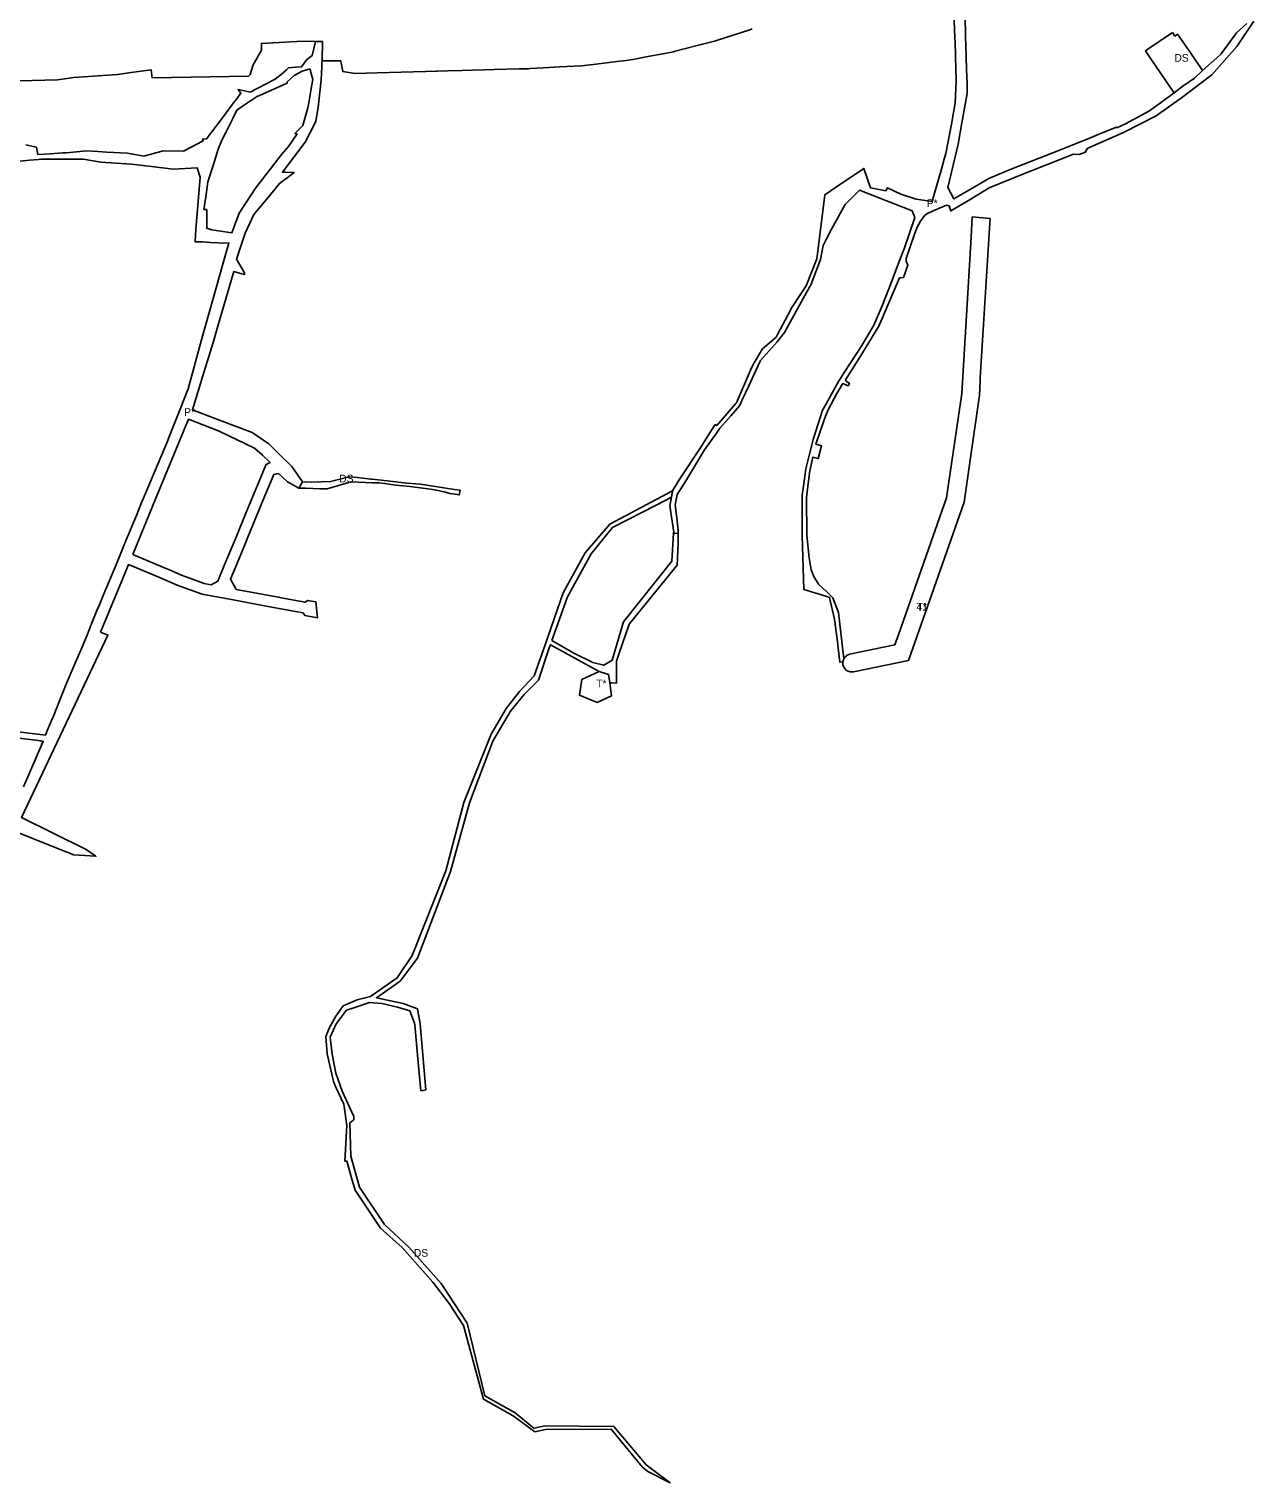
# Model space of a CAD drawing. Extents: x -501732 to -497665, y -1142022 to -1138283.
# Drawn here: x -498822 to -497699, y -1142022 to -1140690 of the extents above; entities that cross this region are included whole.
import ezdxf

# ---------------------------------------------------------------- set-up
doc = ezdxf.new("R2010")
doc.units = 0
for name, color, linetype in [('22', 7, 'Continuous'), ('23', 7, 'Continuous'), ('4', 7, 'Continuous'), ('43', 7, 'Continuous'), ('5', 7, 'Continuous'), ('61', 7, 'Continuous')]:
    doc.layers.add(name, color=color, linetype=linetype)

msp = doc.modelspace()

# ---------------------------------------------------------------- linework, layer by layer
at = {"layer": '22'}
msp.add_lwpolyline([(-498289.435, -1141289.365), (-498287.94, -1141301.37), (-498300.97, -1141307.29), (-498317.15, -1141300.48), (-498315.12, -1141286.35), (-498299.02, -1141279.08), (-498290.41, -1141281.54)], close=True, dxfattribs=at)
at = {"layer": '23'}
msp.add_lwpolyline([(-497940.79, -1140863.814), (-497941.059, -1140868.085), (-497950, -1141010), (-497950.085, -1141012.957), (-497950.453, -1141025.823), (-497959.442, -1141087.571), (-497964.714, -1141123.789), (-497965.056, -1141124.761), (-498015.675, -1141268.789), (-498064.477, -1141278.806), (-498066.144, -1141279.148), (-498069.236, -1141279.192), (-498070.925, -1141278.52), (-498072.345, -1141277.955), (-498074.707, -1141275.584), (-498075.885, -1141272.726), (-498075.895, -1141272.009), (-498075.921, -1141270.104), (-498075.928, -1141269.635), (-498074.954, -1141267.186), (-498074.691, -1141266.526), (-498072.598, -1141264.44), (-498072.32, -1141264.164), (-498069.462, -1141262.986), (-498068.179, -1141262.723), (-498028.144, -1141254.504), (-498024.601, -1141244.424), (-497980.812, -1141119.828), (-497966.901, -1141024.267), (-497958.345, -1140881.029), (-497957.238, -1140862.504), (-497954.3, -1140862.62)], close=True, dxfattribs=at)
at = {"layer": '4'}
for points in [[(-497773.83, -1140693.5), (-497771.55, -1140696.82), (-497769.08, -1140695.11), (-497756.35, -1140713.53), (-497746.3, -1140728.34), (-497753.47, -1140735.53), (-497759.27, -1140739.51), (-497765.07, -1140743.48), (-497772.17, -1140748.77), (-497775.117, -1140744.502), (-497794.317, -1140716.69), (-497798.59, -1140710.5), (-497796.43, -1140708.94)], [(-498574.31, -1141110.9), (-498570.89, -1141105.33), (-498562.596, -1141105.632), (-498545.15, -1141104.99), (-498536.71, -1141102.76), (-498528.28, -1141100.54), (-498520.46, -1141101.35), (-498508.39, -1141102.61), (-498507.39, -1141102.72), (-498498.55, -1141103.7), (-498475.36, -1141106.28), (-498462.89, -1141107.34), (-498431.68, -1141112.08), (-498426.531, -1141112.859), (-498427.26, -1141117.13), (-498433.33, -1141116.09), (-498435.81, -1141115.8), (-498441.2, -1141114.49), (-498449.94, -1141112.38), (-498453.72, -1141111.92), (-498472.53, -1141109.49), (-498478.88, -1141108.76), (-498485.35, -1141108.14), (-498489.86, -1141107.52), (-498495.46, -1141106.76), (-498500.85, -1141106.22), (-498507.19, -1141105.99), (-498513.1, -1141105.94), (-498526.27, -1141105.09), (-498535.71, -1141107.87), (-498548.32, -1141111.71), (-498554.617, -1141111.514), (-498567.931, -1141111.099)], [(-498342.431, -1141250.586), (-498322.306, -1141262), (-498305.064, -1141270.559), (-498294.892, -1141273.288), (-498287.22, -1141268.63), (-498276.94, -1141233.48), (-498232.47, -1141177.75), (-498230.861, -1141152.361), (-498226.765, -1141152.454), (-498226.85, -1141161.49), (-498227.64, -1141181.47), (-498271.5, -1141235.54), (-498275.18, -1141246.2), (-498277.34, -1141252.47), (-498280.96, -1141262.99), (-498283.2, -1141269.48), (-498283.26, -1141289.53), (-498287.32, -1141289.47), (-498289.435, -1141289.365), (-498290.41, -1141281.54), (-498299.02, -1141279.08), (-498343.818, -1141254.467), (-498344.82, -1141257.27), (-498354.69, -1141286.8), (-498367.96, -1141299.96), (-498380.22, -1141315.29), (-498396.49, -1141342.81), (-498418.05, -1141399.23), (-498435.49, -1141462.28), (-498465.58, -1141541.64), (-498481.37, -1141562.54), (-498503.245, -1141577.735), (-498478.577, -1141583.028), (-498465.718, -1141587.813), (-498463.01, -1141601.55), (-498458.03, -1141662.23), (-498460.46, -1141662.63), (-498462.48, -1141662.97), (-498464.9, -1141637.05), (-498468.16, -1141602.47), (-498468.3, -1141600.99), (-498472.52, -1141589.85), (-498483.89, -1141586.39), (-498498.32, -1141583.09), (-498509.53, -1141582.1), (-498523.91, -1141586.93), (-498530.63, -1141589.19), (-498540.19, -1141601.73), (-498545.55, -1141614.01), (-498543.68, -1141629.6), (-498540.35, -1141646.84), (-498534.51, -1141663.26), (-498524.04, -1141686.55), (-498524.02, -1141689.63), (-498527.53, -1141692.29), (-498526.77, -1141723.05), (-498518.8, -1141751.37), (-498495.69, -1141785.66), (-498473.4, -1141806.35), (-498444.04, -1141839.62), (-498420.03, -1141875.81), (-498403.77, -1141942.42), (-498375.96, -1141957.95), (-498358.83, -1141971.96), (-498348.77, -1141970.04), (-498285.68, -1141970.55), (-498256.16, -1142005.55), (-498234.08, -1142022.26), (-498254.59, -1142011.76), (-498259.65, -1142007.67), (-498288.05, -1141973.01), (-498348.22, -1141973.24), (-498358.19, -1141975.54), (-498377.9, -1141960.78), (-498405.21, -1141945.59), (-498423.37, -1141878.17), (-498436.54, -1141857.84), (-498451.59, -1141838.3), (-498479.77, -1141806.48), (-498499.6, -1141788.79), (-498522.72, -1141754.01), (-498525.92, -1141742.8), (-498530.29, -1141727.52), (-498532.03, -1141727.36), (-498530.34, -1141694.84), (-498533.18, -1141675.22), (-498540.46, -1141659.57), (-498542.66, -1141654.6), (-498548.259, -1141629.103), (-498549.654, -1141613.161), (-498546.605, -1141605.539), (-498540.508, -1141594.678), (-498533.648, -1141585.341), (-498520.882, -1141579.815), (-498508.726, -1141576.517), (-498484.13, -1141559.65), (-498470.47, -1141538.96), (-498439.71, -1141461.65), (-498423.24, -1141399.07), (-498398.03, -1141336.42), (-498384.43, -1141312.86), (-498372.17, -1141297.15), (-498358.52, -1141282.97), (-498348.596, -1141254.445), (-498332.09, -1141207), (-498311.8, -1141170.38), (-498289.43, -1141143.87), (-498231.89, -1141113.5), (-498232.81, -1141119.29), (-498246.24, -1141126.218), (-498286.74, -1141147.11), (-498306.4, -1141171.2), (-498328.13, -1141210.57)]]:
    msp.add_lwpolyline(points, close=True, dxfattribs=at)
at = {"layer": '43'}
for points in [[(-497964.62, -1140654.4), (-497963.48, -1140692.74), (-497963.31, -1140698.84), (-497963.1, -1140704.84), (-497962.425, -1140727.105), (-497962.01, -1140740.8), (-497961.95, -1140749.45), (-497966.8, -1140776.46), (-497970.28, -1140795.81), (-497979.66, -1140835.43), (-497974.23, -1140845.84), (-497956.22, -1140835.44), (-497942.02, -1140827.25), (-497922.43, -1140819.22), (-497902.98, -1140811.53), (-497883.42, -1140803.71), (-497862.51, -1140795.48), (-497848.25, -1140789.66), (-497844.06, -1140787.96), (-497838.09, -1140785.5), (-497825.15, -1140780.18), (-497824.82, -1140780.89), (-497816.79, -1140777.36), (-497794.67, -1140765.2), (-497772.17, -1140748.77), (-497765.07, -1140743.48), (-497759.27, -1140739.51), (-497753.47, -1140735.53), (-497746.3, -1140728.34), (-497730.5, -1140714.46), (-497729.76, -1140713.83), (-497729.17, -1140712.99), (-497715.23, -1140693.81), (-497705.51, -1140685.39)], [(-497699.12, -1140683.04), (-497714.85, -1140706.52), (-497737.64, -1140732.37), (-497765.45, -1140753.54), (-497788.84, -1140769.76), (-497818.59, -1140785.2), (-497851.87, -1140799.97), (-497853.39, -1140803.07), (-497859.19, -1140805.3), (-497864.48, -1140804.91), (-497913.92, -1140824.64), (-497920.78, -1140827.42), (-497941.6, -1140835.86), (-497960.66, -1140847.58), (-497977.01, -1140856.97), (-497978.25, -1140852.31), (-497980.78, -1140851.89), (-497993.14, -1140857.08), (-497998.1, -1140859.38), (-498000.68, -1140860.93), (-498004.77, -1140866.35), (-498007.61, -1140872.03), (-498010.54, -1140879.19), (-498017.69, -1140900.56), (-498017.81, -1140902.92), (-498016.39, -1140906.66), (-498020.37, -1140918.16), (-498023.87, -1140918.29), (-498038.33, -1140951.79), (-498042.95, -1140962.63), (-498061.04, -1140992.45), (-498073.33, -1141011.73), (-498072.82, -1141012.92), (-498069.8, -1141015.01), (-498070.83, -1141017.21), (-498075.72, -1141015.23), (-498081.28, -1141024.2), (-498088.95, -1141038.64), (-498091.8, -1141044.92), (-498096.11, -1141057.31), (-498100.54, -1141070.66), (-498095.36, -1141072.27), (-498098.52, -1141083.96), (-498103.39, -1141082.69), (-498106.07, -1141095.04), (-498108.095, -1141111.579), (-498109.11, -1141119.87), (-498108.84, -1141153.98), (-498106.55, -1141174.75), (-498104.84, -1141185.91), (-498102.41, -1141191.82), (-498098.14, -1141198.81), (-498090.9, -1141205.7), (-498084.99, -1141211.46), (-498079.95, -1141225), (-498074.954, -1141267.186), (-498075.928, -1141269.635), (-498075.921, -1141270.104), (-498078.55, -1141270.48), (-498081.13, -1141249.31), (-498083.09, -1141233.44), (-498083.44, -1141230.92), (-498087.32, -1141213.89), (-498087.97, -1141211.13), (-498091.49, -1141210.05), (-498111.43, -1141203.93), (-498113.1, -1141154.31), (-498113.11, -1141150.63), (-498113.18, -1141122.79), (-498113.13, -1141117.32), (-498111.999, -1141109.193), (-498109.78, -1141093.24), (-498102.94, -1141066.53), (-498094.35, -1141039.48), (-498091.41, -1141034.33), (-498079.45, -1141012.67), (-498079.21, -1141012.29), (-498074.51, -1141004.91), (-498058.47, -1140980.44), (-498047.36, -1140961.62), (-498039.9, -1140943.88), (-498031.5, -1140922.99), (-498026.57, -1140909.85), (-498020.61, -1140893.94), (-498020.06, -1140892.7), (-498009.83, -1140863.02), (-498012.27, -1140857), (-498060.53, -1140838.15), (-498073.71, -1140851.2), (-498086.17, -1140873.76), (-498090.72, -1140882.7), (-498093.71, -1140888.57), (-498096.28, -1140901.63), (-498104.91, -1140924.22), (-498112.09, -1140937.34), (-498127.53, -1140965.18), (-498129.24, -1140968.27), (-498135.88, -1140977.02), (-498151.12, -1140993.9), (-498155.49, -1141003.16), (-498162.09, -1141017.13), (-498168.13, -1141029.94), (-498170.6, -1141035.67), (-498178.36, -1141044.85), (-498188.4, -1141055.94), (-498191.645, -1141060.521), (-498202.54, -1141075.9), (-498218.99, -1141103.48), (-498224.74, -1141112.39), (-498227.71, -1141116.93), (-498229.52, -1141126.34), (-498227.94, -1141138.12), (-498226.74, -1141149.75), (-498226.765, -1141152.454), (-498230.861, -1141152.361), (-498230.8, -1141151.4), (-498234.36, -1141127.23), (-498232.81, -1141119.29), (-498231.89, -1141113.5), (-498225.81, -1141103.36), (-498206.05, -1141073.43), (-498196.069, -1141057.817), (-498192.81, -1141052.72), (-498191.37, -1141053.71), (-498174.09, -1141033.85), (-498173.23, -1141032.86), (-498159.51, -1141000.63), (-498157.02, -1140996.31), (-498149.59, -1140983.41), (-498137.06, -1140972.72), (-498135.73, -1140970.18), (-498126.2, -1140952.37), (-498122.42, -1140945.41), (-498114.24, -1140933.03), (-498109.42, -1140925.72), (-498099.64, -1140900.88), (-498098.06, -1140889.02), (-498092.19, -1140842.17), (-498082.41, -1140835.58), (-498056.55, -1140818.15), (-498050.47, -1140835.91), (-498036.37, -1140838.53), (-498035, -1140835.94), (-498022.72, -1140841.59), (-498008.56, -1140846.38), (-497994.03, -1140848.4), (-497992.47, -1140843.02), (-497985.454, -1140818.79), (-497982.83, -1140809.73), (-497981.55, -1140804.44), (-497976.28, -1140777.58), (-497973.02, -1140758.06), (-497972.55, -1140751.57), (-497971.9, -1140737.98), (-497972.51, -1140715.63), (-497972.65, -1140712.12), (-497973.3, -1140696.47), (-497973.452, -1140691.911), (-497973.8, -1140681.43)], [(-498824.4, -1140796.44), (-498814.65, -1140798.62), (-498813.42, -1140805.36), (-498802.05, -1140804.62), (-498790.422, -1140803.871), (-498787.31, -1140803.67), (-498768.83, -1140802.01), (-498758.28, -1140802.69), (-498750.12, -1140803.1), (-498731.35, -1140804.14), (-498716.27, -1140806.99), (-498698.54, -1140801.86), (-498680.14, -1140802.18), (-498662.02, -1140792.71), (-498662.47, -1140791.26), (-498658.87, -1140790.95), (-498644.35, -1140771.71), (-498634.95, -1140759.26), (-498631.56, -1140754.765), (-498627.43, -1140749.29), (-498630.06, -1140745.93), (-498624.23, -1140747.07), (-498618.83, -1140748.13), (-498612.57, -1140744.92), (-498595.88, -1140736.35), (-498594.44, -1140735.17), (-498590.47, -1140731.91), (-498585.66, -1140727.69), (-498583.65, -1140725.93), (-498577.09, -1140725.34), (-498571.85, -1140724.87), (-498567.11, -1140718.32), (-498562.15, -1140714.68), (-498559.063, -1140701.72), (-498552.643, -1140701.808), (-498553.06, -1140719.57), (-498553.11, -1140721.01), (-498553.249, -1140724.759), (-498553.7, -1140736.98), (-498556.49, -1140762.25), (-498558.75, -1140774.89), (-498559.97, -1140777.66), (-498568.52, -1140794.14), (-498589.38, -1140821.38), (-498586.65, -1140821.46), (-498578.61, -1140821.94), (-498584.95, -1140826.56), (-498590.754, -1140830.985), (-498591.98, -1140831.92), (-498602.77, -1140844.93), (-498615.59, -1140860.37), (-498623.59, -1140877.34), (-498630.29, -1140897.47), (-498631.5, -1140901.1), (-498624.03, -1140913.59), (-498624.01, -1140915.23), (-498626.53, -1140914.67), (-498633.99, -1140912.47), (-498647.79, -1140960.45), (-498650.35, -1140969.02), (-498652.268, -1140975.288), (-498655.37, -1140985.43), (-498661.35, -1141005.13), (-498671.72, -1141039.24), (-498649.34, -1141047.78), (-498617.19, -1141060.05), (-498601.76, -1141070.37), (-498596.36, -1141075.85), (-498592.62, -1141079.52), (-498580.66, -1141091.26), (-498570.89, -1141105.33), (-498574.31, -1141110.9), (-498584.82, -1141105.13), (-498592.82, -1141097.64), (-498597.27, -1141098.41), (-498606.94, -1141121.79), (-498616.69, -1141145.36), (-498617.65, -1141147.67), (-498627.58, -1141171.69), (-498636.97, -1141194.38), (-498631.63, -1141203.78), (-498593.1, -1141210.93), (-498590.64, -1141211.38), (-498568.62, -1141215.46), (-498566.29, -1141213.86), (-498558.89, -1141215.23), (-498557.22, -1141229.78), (-498568.84, -1141227.63), (-498570.44, -1141225.29), (-498577.44, -1141224), (-498605.91, -1141218.72), (-498634.37, -1141213.44), (-498662.84, -1141208.17), (-498685.75, -1141199.76), (-498702.71, -1141192.63), (-498730.39, -1141180.99), (-498736.5, -1141195.76), (-498747.91, -1141223.21), (-498756.04, -1141242.78), (-498749.42, -1141245.53), (-498828.34, -1141412.8), (-498769.13, -1141441.85), (-498760.33, -1141448.11), (-498780.88, -1141446.84), (-498784.3, -1141445.42), (-498787.53, -1141444.07), (-498834.17, -1141425.47)], [(-498852.29, -1141331.91), (-498806.51, -1141337.22), (-498805.13, -1141333.9), (-498800.9, -1141323.75), (-498799.25, -1141319.81), (-498793.48, -1141305.96), (-498788.07, -1141292.02), (-498782.2, -1141278.3), (-498773.05, -1141257.17), (-498768.11, -1141244.74), (-498765, -1141236.91), (-498759.27, -1141223.17), (-498757.042, -1141217.827), (-498753.52, -1141209.38), (-498747.93, -1141195.66), (-498742.03, -1141181.8), (-498738.05, -1141172.05), (-498732.41, -1141158.21), (-498730.4, -1141153.42), (-498725.83, -1141142.54), (-498723.14, -1141135.96), (-498718.71, -1141124.96), (-498716.05, -1141118.64), (-498709.32, -1141102.7), (-498694.44, -1141067.19), (-498693.39, -1141064.53), (-498683.14, -1141038.57), (-498675.86, -1141020.14), (-498662.54, -1140971.73), (-498652.1, -1140935.02), (-498641.88, -1140898.03), (-498638.39, -1140886.47), (-498648.5, -1140886.18), (-498655.29, -1140885.89), (-498662.58, -1140885.36), (-498666.89, -1140885.25), (-498669.32, -1140885.19), (-498669.04, -1140879.22), (-498668.56, -1140874.17), (-498664.61, -1140826.24), (-498667.6, -1140817.45), (-498689.33, -1140818.91), (-498711.68, -1140815.95), (-498727.69, -1140814.18), (-498755.74, -1140812.42), (-498771.69, -1140809.65), (-498785.51, -1140809.66), (-498807.56, -1140809.67), (-498810.68, -1140809.67), (-498812.96, -1140809.88), (-498821.01, -1140810.62), (-498829.76, -1140811.43)], [(-498826.65, -1141384.51), (-498809.989, -1141346.416), (-498808.46, -1141342.92), (-498810.61, -1141342.44), (-498830.66, -1141340.16)]]:
    msp.add_lwpolyline(points, dxfattribs=at)
for points in [[(-498585.06, -1140740), (-498613.13, -1140752.37), (-498624.143, -1140759.975), (-498631, -1140764.71), (-498634.79, -1140772.22), (-498641.02, -1140784.54), (-498643.91, -1140790.25), (-498646.275, -1140795.946), (-498648.12, -1140800.39), (-498652.59, -1140814.37), (-498657.75, -1140830.51), (-498659.61, -1140844.08), (-498661.43, -1140855.69), (-498658.76, -1140855.73), (-498658.72, -1140868.76), (-498658.71, -1140871.84), (-498658.71, -1140872.83), (-498653.91, -1140874.46), (-498635.81, -1140877.1), (-498628.95, -1140859.03), (-498618.06, -1140842.32), (-498614.08, -1140836.21), (-498614, -1140836.09), (-498600.26, -1140818.353), (-498593.17, -1140809.2), (-498589.99, -1140805.1), (-498588.18, -1140802.76), (-498583.88, -1140797.92), (-498575.94, -1140786.43), (-498577.86, -1140786.01), (-498570.78, -1140778.71), (-498565.98, -1140762.6), (-498565.19, -1140757.89), (-498562.73, -1140743.15), (-498561.64, -1140736.64), (-498563.21, -1140730.16), (-498564, -1140726.92), (-498571.27, -1140728.89), (-498578.71, -1140733.02), (-498584.91, -1140738.9)], [(-498726.58, -1141171.76), (-498698.91, -1141183.44), (-498692.26, -1141186.25), (-498681.82, -1141190.57), (-498661.02, -1141198.34), (-498654.68, -1141199.51), (-498648.54, -1141196.2), (-498642.63, -1141181.9), (-498632.69, -1141157.87), (-498630.66, -1141152.97), (-498622.75, -1141133.84), (-498612.81, -1141109.82), (-498604.89, -1141090.66), (-498604.28, -1141089.18), (-498600.604, -1141087.356), (-498607.65, -1141080.852), (-498614.843, -1141074.213), (-498647.32, -1141058.63), (-498675.34, -1141047.9), (-498690.63, -1141084.87), (-498705.92, -1141121.83), (-498716.3, -1141146.93)]]:
    msp.add_lwpolyline(points, close=True, dxfattribs=at)
at = {"layer": '5'}
msp.add_lwpolyline([(-498158.761, -1140690.084), (-498161.095, -1140690.981), (-498190.601, -1140700.559), (-498192.164, -1140701.066), (-498210.389, -1140705.834), (-498219.943, -1140708.334), (-498229.365, -1140710.799), (-498231.078, -1140711.132), (-498242.417, -1140713.334), (-498252.872, -1140715.365), (-498268.347, -1140718.37), (-498274.437, -1140719.123), (-498283.056, -1140720.189), (-498294.735, -1140721.634), (-498304.746, -1140722.872), (-498312.551, -1140723.837), (-498315.16, -1140723.983), (-498315.351, -1140723.994), (-498335.52, -1140725.126), (-498335.576, -1140725.129), (-498350.18, -1140725.948), (-498362.193, -1140726.622), (-498363.866, -1140726.716), (-498372.437, -1140726.953), (-498395.246, -1140727.586), (-498404.381, -1140727.839), (-498415.103, -1140728.136), (-498424.822, -1140728.405), (-498438.021, -1140728.758), (-498447.686, -1140729.016), (-498448.223, -1140729.03), (-498457.932, -1140729.289), (-498458.141, -1140729.295), (-498502.393, -1140730.477), (-498522.815, -1140731.022), (-498534.089, -1140729.416), (-498535.16, -1140723.08), (-498535.79, -1140719.63), (-498553.06, -1140719.57), (-498552.643, -1140701.808), (-498559.063, -1140701.72), (-498566.41, -1140701.62), (-498576.28, -1140701.95), (-498608.546, -1140703.543), (-498608.67, -1140709.77), (-498616.02, -1140723.18), (-498619.06, -1140731.91), (-498620.29, -1140733.478), (-498708.816, -1140735.001), (-498709.65, -1140727.63), (-498725.72, -1140729.92), (-498740.49, -1140732.02), (-498780.63, -1140734.94), (-498795.52, -1140736.85), (-498853.837, -1140738.595)], dxfattribs=at)

# ---------------------------------------------------------------- texts
at = {"layer": '22'}
msp.add_text('T*', height=7, dxfattribs=at).set_placement((-498301.792, -1141293.331))
at = {"layer": '23'}
msp.add_text('T*', height=7, dxfattribs=at).set_placement((-498008.299, -1141223.085))
at = {"layer": '4'}
for p in [(-497771.953, -1140720.294), (-498537.282, -1141105.648), (-498468.848, -1141815.06)]:
    msp.add_text('DS', height=7, dxfattribs=at).set_placement(p)
at = {"layer": '43'}
for p in [(-497998.95, -1140853.398), (-498679.311, -1141044.762)]:
    msp.add_text('P*', height=7, dxfattribs=at).set_placement(p)
at = {"layer": '61'}
msp.add_text('41', height=7, dxfattribs=at).set_placement((-498008.291, -1141223.085))

doc.saveas('drawing.dxf')
